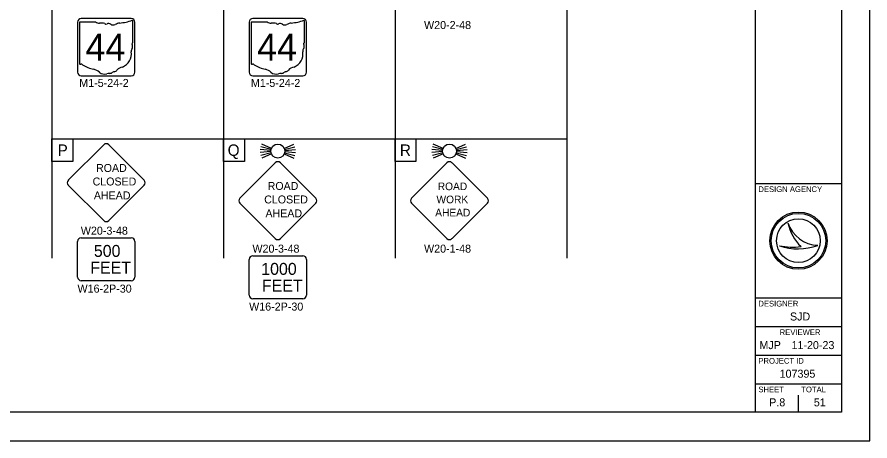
# Model space of a CAD drawing. Extents: x 0 to 34, y 0 to 22.
# Drawn here: x 19.09 to 34, y 0 to 7.41 of the extents above; entities that cross this region are included whole.
import ezdxf

# ---------------------------------------------------------------- set-up
doc = ezdxf.new("R2010")
doc.units = 0
for name, color, linetype in [('SC_Scratch1', 7, 'Continuous'), ('SH_Border', 7, 'Continuous'), ('SH_Cut_Line', 7, 'Continuous'), ('SH_Data', 7, 'Continuous'), ('SH_Text', 7, 'Continuous'), ('SN_P_Signs', 7, 'Continuous'), ('SN_P_Text', 7, 'Continuous')]:
    doc.layers.add(name, color=color, linetype=linetype)

msp = doc.modelspace()

# ---------------------------------------------------------------- linework, layer by layer
at = {"layer": 'SC_Scratch1'}
for p, q in [((19.701, 21.282), (19.701, 3.194)), ((22.701, 21.282), (22.701, 3.194)), ((25.701, 21.282), (25.701, 3.194)), ((28.701, 21.282), (28.701, 3.194)), ((19.701, 5.282), (28.701, 5.282))]:
    msp.add_line(p, q, dxfattribs=at)
at = {"layer": 'SH_Border'}
for p, q in [((32, 0.5), (32, 21.5)), ((32, 4.5), (33.5, 4.5)), ((32, 2.5), (33.5, 2.5)), ((32, 2), (33.5, 2)), ((32, 1.5), (33.5, 1.5)), ((32, 1), (33.5, 1))]:
    msp.add_line(p, q, dxfattribs=at)
msp.add_lwpolyline([(1.5, 21.5), (33.5, 21.5), (33.5, 0.5), (1.5, 0.5)], close=True, dxfattribs=at)
at = {"layer": 'SH_Cut_Line'}
msp.add_lwpolyline([(0, 0), (34, 0), (34, 22), (0, 22)], close=True, dxfattribs=at)
at = {"layer": 'SH_Data'}
for p, q in [((32.567, 3.81), (32.567, 3.81)), ((32.75, 3.5), (32.75, 3.5)), ((32.417, 3.41), (32.417, 3.41)), ((33.087, 3.419), (33.087, 3.419)), ((32.75, 0.5), (32.75, 0.8)), ((32.375, 0.675), (32.375, 0.675))]:
    msp.add_line(p, q, dxfattribs=at)
for radius in [0.5, 0.477, 0.477, 0.382]:
    msp.add_circle((32.75, 3.5), radius, dxfattribs=at)
for centre, radius, start, end in [((33.116, 3.998), 0.58, 198.9257, 198.9319), ((33.347, 3.97), 0.796, 191.6379, 191.6421), ((33.116, 3.998), 0.58, 198.9319, 267.1657), ((33.347, 3.97), 0.796, 191.6421, 226.0947), ((32.739, 4.37), 1.013, 251.4576, 290.0832), ((32.648, 4.654), 1.266, 259.4964, 259.4995), ((32.739, 4.37), 1.013, 251.4527, 251.4576), ((32.648, 4.654), 1.266, 259.4995, 276.6672)]:
    msp.add_arc(centre, radius, start, end, dxfattribs=at)
at = {"layer": 'SH_Text'}
for p, q in [((23.528, 5.076), (23.343, 5.091)), ((23.531, 5.095), (23.351, 5.141)), ((23.537, 5.114), (23.367, 5.188)), ((23.761, 5.114), (23.931, 5.188)), ((23.768, 5.095), (23.947, 5.141)), ((23.771, 5.076), (23.956, 5.091)), ((26.528, 5.076), (26.343, 5.091)), ((26.531, 5.095), (26.351, 5.141)), ((26.537, 5.114), (26.367, 5.188)), ((26.761, 5.114), (26.931, 5.188)), ((26.768, 5.095), (26.947, 5.141)), ((26.771, 5.076), (26.956, 5.091)), ((23.528, 5.056), (23.343, 5.041)), ((23.531, 5.036), (23.351, 4.991)), ((23.537, 5.017), (23.367, 4.943)), ((23.761, 5.017), (23.931, 4.943)), ((23.768, 5.036), (23.947, 4.991)), ((23.771, 5.056), (23.956, 5.041)), ((26.528, 5.056), (26.343, 5.041)), ((26.531, 5.036), (26.351, 4.991)), ((26.537, 5.017), (26.367, 4.943)), ((26.761, 5.017), (26.931, 4.943)), ((26.768, 5.036), (26.947, 4.991)), ((26.771, 5.056), (26.956, 5.041))]:
    msp.add_line(p, q, dxfattribs=at)
for points in [[(19.701, 5.282), (20.064, 5.282), (20.064, 4.882), (19.701, 4.882)], [(22.701, 5.282), (23.064, 5.282), (23.064, 4.882), (22.701, 4.882)], [(25.701, 5.282), (26.064, 5.282), (26.064, 4.882), (25.701, 4.882)]]:
    msp.add_lwpolyline(points, close=True, dxfattribs=at)
for centre in [(23.649, 5.066), (26.649, 5.066)]:
    msp.add_circle(centre, 0.122, dxfattribs=at)
at = {"layer": 'SN_P_Signs'}
for p, q in [((20.18, 7.31), (20.18, 6.598)), ((20.464, 7.322), (20.189, 7.322)), ((21.117, 6.967), (21.117, 7.34)), ((23.18, 7.31), (23.18, 6.598)), ((23.464, 7.322), (23.189, 7.322)), ((24.117, 6.967), (24.117, 7.34)), ((21.117, 6.968), (21.117, 6.967)), ((24.117, 6.968), (24.117, 6.967))]:
    msp.add_line(p, q, dxfattribs=at)
for points in [[(20.149, 7.319), (20.149, 6.444)], [(21.087, 7.382), (20.212, 7.382)], [(21.149, 6.444), (21.149, 7.319)], [(23.149, 7.319), (23.149, 6.444)], [(24.087, 7.382), (23.212, 7.382)], [(24.149, 6.444), (24.149, 7.319)], [(20.212, 6.382), (21.087, 6.382)], [(23.212, 6.382), (24.087, 6.382)], [(19.986, 4.558), (20.605, 5.176)], [(20.694, 5.176), (21.312, 4.558)], [(22.986, 4.244), (23.605, 4.862)], [(23.694, 4.862), (24.312, 4.244)], [(25.986, 4.244), (26.605, 4.862)], [(26.694, 4.862), (27.312, 4.244)], [(20.605, 3.85), (19.986, 4.469)], [(21.312, 4.469), (20.694, 3.85)], [(23.605, 3.536), (22.986, 4.155)], [(24.312, 4.155), (23.694, 3.536)], [(26.605, 3.536), (25.986, 4.155)], [(27.312, 4.155), (26.694, 3.536)], [(20.149, 2.863), (20.149, 3.488)], [(20.212, 3.55), (21.087, 3.55)], [(21.149, 3.488), (21.149, 2.863)], [(23.149, 2.549), (23.149, 3.174)], [(23.212, 3.236), (24.087, 3.236)], [(24.149, 3.174), (24.149, 2.549)], [(21.087, 2.8), (20.212, 2.8)], [(24.087, 2.486), (23.212, 2.486)]]:
    msp.add_lwpolyline(points, dxfattribs=at)
for centre, radius, start, end in [((20.212, 7.319), 0.0625, 90, 180), ((20.191, 7.311), 0.0109, 98.1301, 188.1301), ((20.529, 7.405), 0.105, 231.6195, 271.1119), ((20.783, 8.292), 0.994, 275.8445, 288.9065), ((21.087, 7.319), 0.0625, 0, 90), ((21.107, 7.341), 0.0104, 351.8621, 97.738), ((23.212, 7.319), 0.0625, 90, 180), ((23.191, 7.311), 0.0109, 98.1301, 188.1301), ((23.529, 7.405), 0.105, 231.6195, 271.1119), ((23.783, 8.292), 0.994, 275.8445, 288.9065), ((24.087, 7.319), 0.0625, 0, 90), ((24.107, 7.341), 0.0104, 351.8621, 97.738), ((20.564, 6.923), 0.378, 80.4867, 94.9883), ((20.65, 7.315), 0.0304, 219.7921, 297.1024), ((20.694, 7.233), 0.0632, 54.4667, 119.1411), ((20.776, 7.346), 0.076, 233.8562, 294.8282), ((20.91, 7.105), 0.2, 97.3462, 120.7689), ((23.564, 6.923), 0.378, 80.4867, 94.9883), ((23.65, 7.315), 0.0304, 219.7921, 297.1024), ((23.694, 7.233), 0.0632, 54.4667, 119.1411), ((23.776, 7.346), 0.076, 233.8562, 294.8282), ((23.91, 7.105), 0.2, 97.3462, 120.7689), ((21.155, 6.812), 0.0705, 136.8065, 186.9296), ((21.115, 6.94), 0.0162, 107.944, 210.337), ((21.012, 6.893), 0.097, 340.033, 23.6496), ((21.106, 6.966), 0.0112, 289.6038, 7.7341), ((24.155, 6.812), 0.0705, 136.8065, 186.9296), ((24.115, 6.94), 0.0162, 107.944, 210.337), ((24.012, 6.893), 0.097, 340.033, 23.6496), ((24.106, 6.966), 0.0112, 289.6038, 7.7341), ((20.839, 6.764), 0.249, 292.3089, 8.9858), ((23.839, 6.764), 0.249, 292.3089, 8.9858), ((20.191, 6.597), 0.011, 171.9584, 258.3066), ((20.192, 6.669), 0.0836, 267.339, 280.6039), ((20.209, 6.557), 0.0302, 29.7484, 93.2717), ((20.59, 7.196), 0.718, 240.4129, 257.1985), ((23.191, 6.597), 0.011, 171.9584, 258.3066), ((23.192, 6.669), 0.0836, 267.339, 280.6039), ((23.209, 6.557), 0.0302, 29.7484, 93.2717), ((23.59, 7.196), 0.718, 240.4129, 257.1985), ((20.212, 6.444), 0.0625, 180, 270), ((20.376, 6.279), 0.225, 47.1842, 75.836), ((20.619, 6.554), 0.143, 230.7004, 286.2918), ((20.701, 6.308), 0.117, 85.6951, 111.2099), ((20.712, 6.5), 0.0759, 268.777, 315.5493), ((20.781, 6.431), 0.0214, 65.7517, 132.6484), ((20.771, 6.529), 0.0803, 282.8732, 323.2771), ((20.944, 6.398), 0.136, 94.4031, 142.5768), ((21.087, 6.444), 0.0625, 270, 0), ((23.212, 6.444), 0.0625, 180, 270), ((23.376, 6.279), 0.225, 47.1842, 75.836), ((23.619, 6.554), 0.143, 230.7004, 286.2918), ((23.701, 6.308), 0.117, 85.6951, 111.2099), ((23.712, 6.5), 0.0759, 268.777, 315.5493), ((23.781, 6.431), 0.0214, 65.7517, 132.6484), ((23.771, 6.529), 0.0803, 282.8732, 323.2771), ((23.944, 6.398), 0.136, 94.4031, 142.5768), ((24.087, 6.444), 0.0625, 270, 0), ((20.649, 5.132), 0.0625, 45, 135), ((23.649, 4.818), 0.0625, 45, 135), ((26.649, 4.818), 0.0625, 45, 135), ((20.031, 4.513), 0.0625, 135, 225), ((21.268, 4.513), 0.0625, 315, 45), ((23.031, 4.199), 0.0625, 135, 225), ((24.268, 4.199), 0.0625, 315, 45), ((26.031, 4.199), 0.0625, 135, 225), ((27.268, 4.199), 0.0625, 315, 45), ((20.649, 3.895), 0.0625, 225, 315), ((20.212, 3.488), 0.0625, 90, 180), ((21.087, 3.488), 0.0625, 0, 90), ((23.649, 3.581), 0.0625, 225, 315), ((26.649, 3.581), 0.0625, 225, 315), ((23.212, 3.174), 0.0625, 90, 180), ((24.087, 3.174), 0.0625, 0, 90), ((20.212, 2.863), 0.0625, 180, 270), ((21.087, 2.863), 0.0625, 270, 0), ((23.212, 2.549), 0.0625, 180, 270), ((24.087, 2.549), 0.0625, 270, 0)]:
    msp.add_arc(centre, radius, start, end, dxfattribs=at)

# ---------------------------------------------------------------- texts
at = {"layer": 'SH_Data'}
for s, height, p in [('DESIGN AGENCY', 0.1, (32.05, 4.35)), ('DESIGNER', 0.1, (32.05, 2.35)), ('SJD', 0.14, (32.602, 2.105)), ('REVIEWER', 0.1, (32.422, 1.85)), ('MJP', 0.14, (32.068, 1.605)), ('11-20-23', 0.14, (32.629, 1.605)), ('PROJECT ID', 0.1, (32.05, 1.35)), ('107395', 0.14, (32.421, 1.105)), ('SHEET', 0.1, (32.05, 0.85)), ('TOTAL', 0.1, (32.8, 0.85)), ('P.8', 0.14, (32.239, 0.605)), ('51', 0.14, (33.019, 0.605))]:
    msp.add_text(s, height=height, dxfattribs=at).set_placement(p)
at = {"layer": 'SH_Text'}
for s, p in [('P', (19.799, 4.982)), ('Q', (22.772, 4.982)), ('R', (25.782, 4.982))]:
    msp.add_text(s, height=0.2, dxfattribs=at).set_placement(p)
at = {"layer": 'SN_P_Signs'}
for s, height, p in [('44', 0.4688, (20.286, 6.648)), ('44', 0.4688, (23.286, 6.648)), ('ROAD', 0.1389, (20.471, 4.701)), ('CLOSED', 0.1389, (20.411, 4.465)), ('ROAD', 0.1389, (23.471, 4.387)), ('ROAD', 0.1333, (26.444, 4.383)), ('AHEAD', 0.1389, (20.433, 4.222)), ('CLOSED', 0.1389, (23.411, 4.151)), ('WORK', 0.1333, (26.422, 4.154)), ('AHEAD', 0.1389, (23.433, 3.908)), ('AHEAD', 0.1333, (26.4, 3.924)), ('500', 0.2083, (20.433, 3.217)), ('FEET', 0.2083, (20.37, 2.925)), ('1000', 0.2083, (23.359, 2.903)), ('FEET', 0.2083, (23.37, 2.611))]:
    msp.add_text(s, height=height, dxfattribs=at).set_placement(p)
at = {"layer": 'SN_P_Text'}
for s, p in [('W20-2-48', (26.205, 7.199)), ('M1-5-24-2', (20.178, 6.187)), ('M1-5-24-2', (23.178, 6.187)), ('W20-3-48', (20.205, 3.605)), ('W20-3-48', (23.205, 3.291)), ('W20-1-48', (26.205, 3.291)), ('W16-2P-30', (20.147, 2.592)), ('W16-2P-30', (23.147, 2.278))]:
    msp.add_text(s, height=0.14, dxfattribs=at).set_placement(p)

doc.saveas('drawing.dxf')
